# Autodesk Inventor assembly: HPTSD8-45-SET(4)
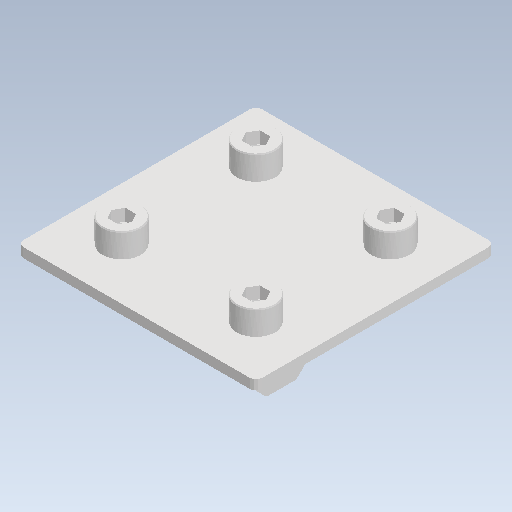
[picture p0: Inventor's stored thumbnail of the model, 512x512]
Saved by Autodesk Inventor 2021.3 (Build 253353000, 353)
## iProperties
Created: 2022-02
Part Number: HPTSD8-45-SET(4)
Document SubType Name: Assembly
Designer: kengo
Author: kengo
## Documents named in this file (4)
- C:\Users\kengo\Documents\S2S_frame\SDC345\frame_misumi_ver12\HPTSD8-45-SET(4).iam
- C:\Users\kengo\Documents\S2S_frame\SDC345\frame_misumi_ver12\HPTSD8-45.ipt
- C:\Users\kengo\Documents\S2S_frame\SDC345\frame_misumi_ver12\HNTT8-8.ipt
- C:\Users\kengo\Documents\S2S_frame\SDC345\frame_misumi_ver12\CBM8-15.ipt
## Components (9 placed, 3 different names)
1. HPTSD8-45
2. HNTT8-8
3. CBM8-15
4. HNTT8-8:1
5. CBM8-15:1
6. HNTT8-8:2
7. CBM8-15:2
8. HNTT8-8:3
9. CBM8-15:3
